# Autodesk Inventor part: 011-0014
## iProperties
Created: 2007-02
Part Number: 011-0014
Document SubType Name: Modeling
Designer: GG5883
Material: 34 Cr Mo 4
Description: Mors mobile
Stock Number: 11-0014
Checked By: GG5883
Author: GG5883
Revision Number: 00
Title: MORS MOBILE
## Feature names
1. Volume base [Extrusion]
2. Perçages fixation mors [Hole]
3. Extrusion4
